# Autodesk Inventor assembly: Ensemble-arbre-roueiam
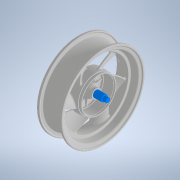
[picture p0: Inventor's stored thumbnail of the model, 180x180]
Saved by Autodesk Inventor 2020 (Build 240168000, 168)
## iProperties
Created: 2020-09
Part Number: Ensemble-arbre-roueiam
Document SubType Name: Assembly
Designer: Bruno
Author: Bruno
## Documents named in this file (3)
- D:\Téléchargements-2016-17\scoot_elec\Ensemble-arbre-roueiam.iam
- D:\Téléchargements-2016-17\scoot_elec\pièces à assembler\Arbre de sortie.ipt
- D:\Téléchargements-2016-17\scoot_elec\pièces à assembler\Jante.ipt
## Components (2 placed, 2 different names)
1. Arbre de sortie:1 — Placage:1
2. Jante:1 — Placage:1
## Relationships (1: Mate 1)
- Placage:1 [Mate]: Arbre de sortie:1 ↔ Jante:1
